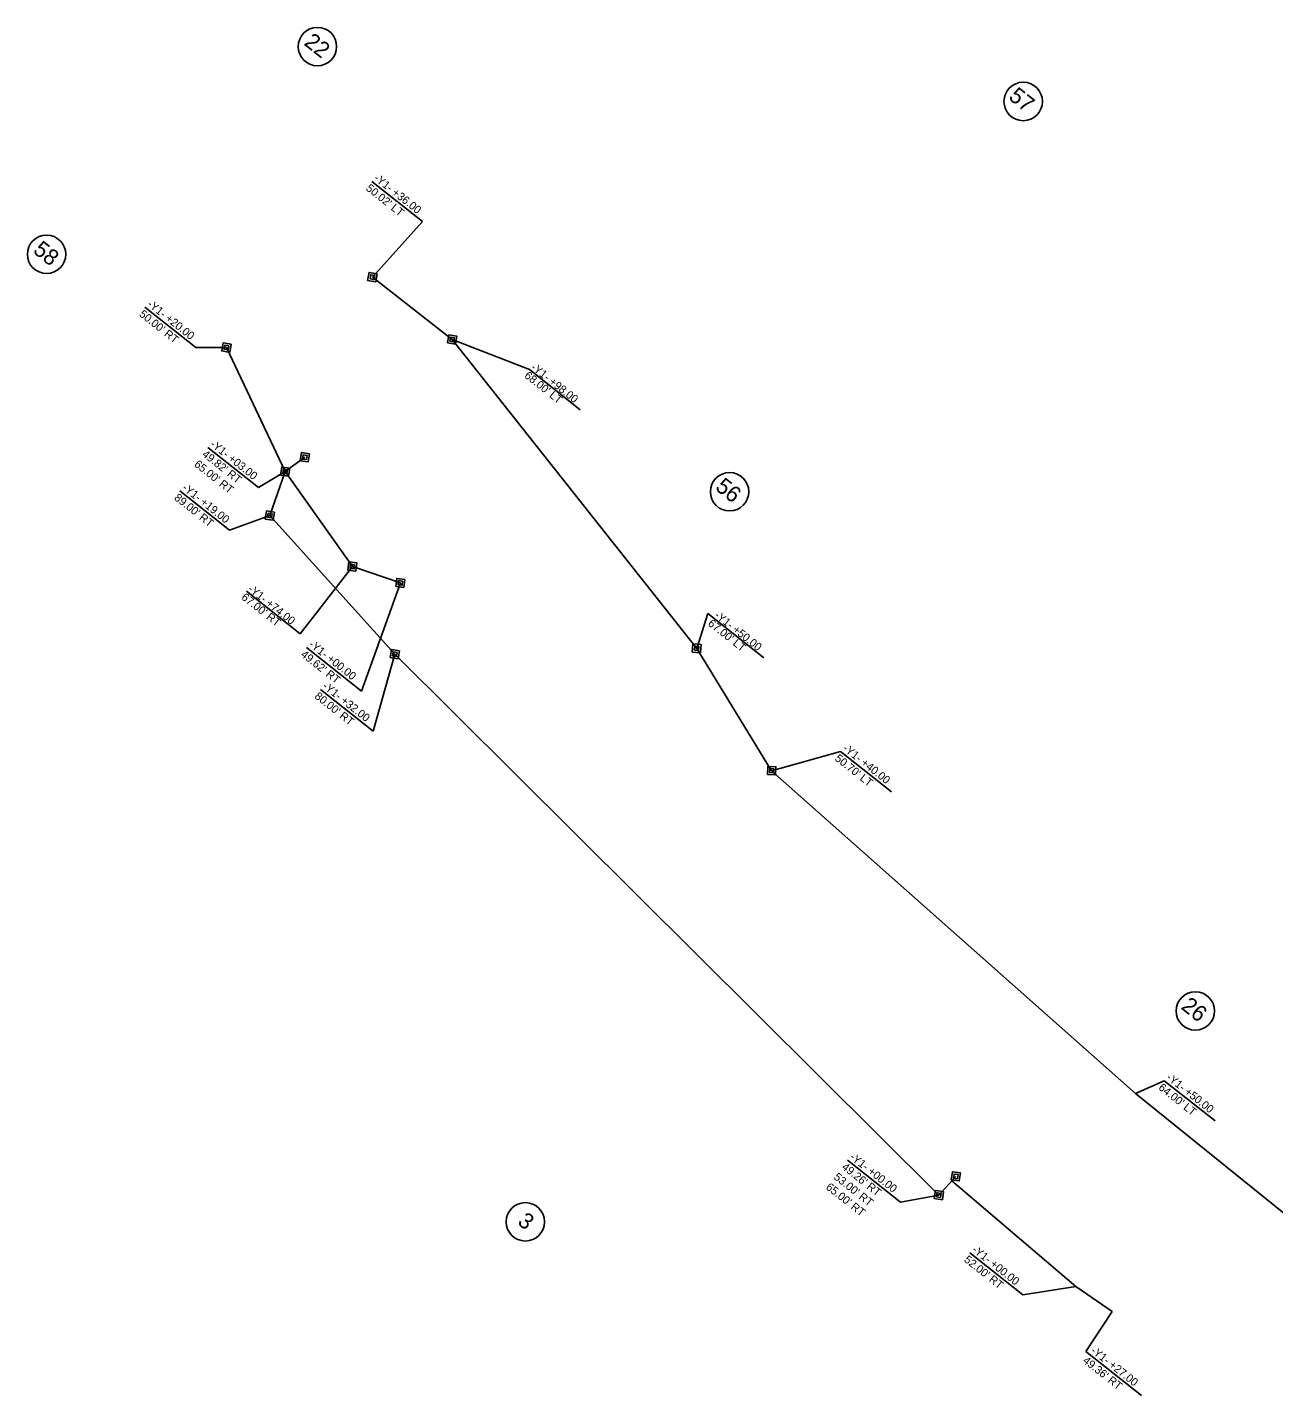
# Model space of a CAD drawing. Extents: x 1779796 to 1783527, y 810952 to 815815.
# Drawn here: x 1781662 to 1782441, y 814394 to 815249 of the extents above; entities that cross this region are included whole.
import ezdxf

# ---------------------------------------------------------------- set-up
doc = ezdxf.new("R2010")
doc.units = 0
for name, color, linetype in [('Prop Easement Construction', 7, 'Continuous'), ('Prop Easement Construction Station Offsets', 7, 'Continuous'), ('Prop Easement Permanent Drainage', 7, 'Continuous'), ('Prop Easement Permanent Drainage Station Offsets', 7, 'Continuous'), ('Prop Easement Permanent Drainage Utility', 7, 'Continuous'), ('Prop Easement Permanent Drainage Utility Station Offsets', 7, 'Continuous'), ('Prop Easement Permanent Utility', 7, 'Continuous'), ('Prop Easement Permanent Utility Station Offsets', 7, 'Continuous'), ('Prop Parcel Number CELL', 7, 'Continuous'), ('Prop Parcel Number Text', 7, 'Continuous'), ('Prop ROW Marker CELL', 7, 'Continuous'), ('Prop ROW Permanent Easement CELL', 7, 'Continuous')]:
    doc.layers.add(name, color=color, linetype=linetype)

msp = doc.modelspace()

# ---------------------------------------------------------------- linework, layer by layer
at = {"layer": 'Prop Easement Construction'}
for p, q in [((1782126.93, 814784.65), (1782354.41, 814582.96)), ((1782354.41, 814582.96), (1782533.17, 814438.56)), ((1782239.52, 814528.39), (1782317, 814462.35)), ((1782317, 814462.35), (1782339.81, 814446.82))]:
    msp.add_line(p, q, dxfattribs=at)
at = {"layer": 'Prop Easement Construction Station Offsets'}
for p, q in [((1782404.05, 814565.8), (1782372.27, 814590.96)), ((1782283.82, 814457.22), (1782250.76, 814483.39)), ((1782283.82, 814457.22), (1782317, 814462.35)), ((1782323.29, 814421.68), (1782339.81, 814446.82)), ((1782358.05, 814394.16), (1782323.29, 814421.68))]:
    msp.add_line(p, q, dxfattribs=at)
msp.add_lwpolyline([(1782372.27, 814590.96), (1782354.41, 814582.96)], dxfattribs=at)
at = {"layer": 'Prop Easement Permanent Drainage'}
for p, q in [((1781877.43, 815093.01), (1781927.33, 815054)), ((1781927.33, 815054), (1782080.08, 814861.09)), ((1781786.2, 815049), (1781822.91, 814971.49)), ((1782080.08, 814861.09), (1782126.93, 814784.65))]:
    msp.add_line(p, q, dxfattribs=at)
at = {"layer": 'Prop Easement Permanent Drainage Station Offsets'}
for p, q in [((1781908.79, 815127.71), (1781877, 815152.87)), ((1781767.08, 815049.02), (1781735.3, 815074.19)), ((1782007.33, 815010.08), (1781975.55, 815035.24)), ((1782122.04, 814855.18), (1782087.14, 814882.81)), ((1782201.84, 814771.45), (1782170.06, 814796.61))]:
    msp.add_line(p, q, dxfattribs=at)
for points in [[(1781908.79, 815127.71), (1781877.43, 815093.01)], [(1781975.55, 815035.24), (1781927.33, 815054)], [(1781767.08, 815049.02), (1781786.2, 815049)], [(1782087.14, 814882.81), (1782080.08, 814861.09)], [(1782170.06, 814796.61), (1782126.93, 814784.65)]]:
    msp.add_lwpolyline(points, dxfattribs=at)
at = {"layer": 'Prop Easement Permanent Drainage Utility'}
for p, q in [((1781835.16, 814980.46), (1781822.91, 814971.49)), ((1781822.91, 814971.49), (1781864.92, 814912.23)), ((1781864.92, 814912.23), (1781894.93, 814901.96))]:
    msp.add_line(p, q, dxfattribs=at)
at = {"layer": 'Prop Easement Permanent Drainage Utility Station Offsets'}
for p, q in [((1781806.32, 814961.57), (1781774.63, 814986.66)), ((1781832.29, 814870.15), (1781798.69, 814896.76)), ((1781870.63, 814834.39), (1781836.31, 814861.56))]:
    msp.add_line(p, q, dxfattribs=at)
for points in [[(1781806.32, 814961.57), (1781822.91, 814971.49)], [(1781832.29, 814870.15), (1781864.92, 814912.23)], [(1781870.63, 814834.39), (1781894.93, 814901.96)]]:
    msp.add_lwpolyline(points, dxfattribs=at)
at = {"layer": 'Prop Easement Permanent Utility'}
for p, q in [((1781822.91, 814971.49), (1781813.32, 814944.03)), ((1781813.32, 814944.03), (1781891.47, 814857.45)), ((1781891.47, 814857.45), (1782231.49, 814519.48)), ((1782231.49, 814519.48), (1782242.01, 814531.17))]:
    msp.add_line(p, q, dxfattribs=at)
at = {"layer": 'Prop Easement Permanent Utility Station Offsets'}
for p, q in [((1781788.04, 814935.03), (1781757.19, 814959.45)), ((1781877.97, 814809.3), (1781891.47, 814857.45)), ((1781877.97, 814809.3), (1781844.91, 814835.47)), ((1782207.41, 814515.14), (1782174.35, 814541.32)), ((1782207.41, 814515.14), (1782231.49, 814519.48))]:
    msp.add_line(p, q, dxfattribs=at)
msp.add_lwpolyline([(1781788.04, 814935.03), (1781813.32, 814944.03)], dxfattribs=at)
at = {"layer": 'Prop Parcel Number CELL'}
for p, q in [((1781843.08, 815237.09), (1781843.08, 815237.09)), ((1782284.14, 815202.78), (1782284.14, 815202.78)), ((1781673.8, 815107.31), (1781673.8, 815107.31)), ((1782100.63, 814958.93), (1782100.63, 814958.93)), ((1782391.73, 814634.53), (1782391.73, 814634.53)), ((1781973.02, 814502.77), (1781973.02, 814502.77))]:
    msp.add_line(p, q, dxfattribs=at)
for centre in [(1781843.08, 815237.09), (1782284.14, 815202.78), (1781673.8, 815107.31), (1782100.63, 814958.93), (1782391.73, 814634.53), (1781973.02, 814502.77)]:
    msp.add_circle(centre, 12, dxfattribs=at)
at = {"layer": 'Prop ROW Marker CELL'}
for p, q in [((1781877.43, 815093.01), (1781877.43, 815093.01)), ((1781927.33, 815054), (1781927.33, 815054)), ((1781786.2, 815049), (1781786.2, 815049)), ((1781835.16, 814980.46), (1781835.16, 814980.46)), ((1781822.91, 814971.49), (1781822.91, 814971.49)), ((1781813.32, 814944.03), (1781813.32, 814944.03)), ((1781864.92, 814912.23), (1781864.92, 814912.23)), ((1781894.93, 814901.96), (1781894.93, 814901.96)), ((1781891.47, 814857.45), (1781891.47, 814857.45)), ((1782080.08, 814861.09), (1782080.08, 814861.09)), ((1782126.93, 814784.65), (1782126.93, 814784.65)), ((1782242.01, 814531.17), (1782242.01, 814531.17)), ((1782231.49, 814519.48), (1782231.49, 814519.48))]:
    msp.add_line(p, q, dxfattribs=at)
at = {"layer": 'Prop ROW Permanent Easement CELL'}
for points in [[(1781874.47, 815090.95), (1781875.37, 815095.96), (1781880.38, 815095.07), (1781879.49, 815090.06)], [(1781875.95, 815091.98), (1781876.4, 815094.49), (1781878.9, 815094.04), (1781878.46, 815091.53)], [(1781789.16, 815051.05), (1781788.26, 815046.04), (1781783.25, 815046.94), (1781784.15, 815051.95)], [(1781787.68, 815050.03), (1781787.23, 815047.52), (1781784.73, 815047.97), (1781785.18, 815050.48)], [(1781924.43, 815051.88), (1781925.21, 815056.91), (1781930.24, 815056.13), (1781929.46, 815051.1)], [(1781925.88, 815052.94), (1781926.27, 815055.46), (1781928.79, 815055.06), (1781928.39, 815052.55)], [(1781838.06, 814982.58), (1781837.29, 814977.55), (1781832.26, 814978.33), (1781833.03, 814983.36)], [(1781836.61, 814981.52), (1781836.22, 814979.01), (1781833.71, 814979.39), (1781834.09, 814981.91)], [(1781825.81, 814973.62), (1781825.04, 814968.59), (1781820.01, 814969.35), (1781820.77, 814974.39)], [(1781824.36, 814972.55), (1781823.97, 814970.04), (1781821.46, 814970.42), (1781821.84, 814972.94)], [(1781816.22, 814946.17), (1781815.46, 814941.14), (1781810.43, 814941.89), (1781811.18, 814946.92)], [(1781814.77, 814945.1), (1781814.39, 814942.58), (1781811.88, 814942.96), (1781812.25, 814945.48)], [(1781867.77, 814914.43), (1781867.12, 814909.38), (1781862.07, 814910.03), (1781862.72, 814915.08)], [(1781866.35, 814913.33), (1781866.02, 814910.8), (1781863.5, 814911.13), (1781863.82, 814913.65)], [(1781897.76, 814904.19), (1781897.15, 814899.13), (1781892.1, 814899.74), (1781892.7, 814904.8)], [(1781896.34, 814903.08), (1781896.04, 814900.55), (1781893.51, 814900.85), (1781893.82, 814903.38)], [(1782077.36, 814858.73), (1782077.71, 814863.81), (1782082.79, 814863.46), (1782082.44, 814858.38)], [(1782078.72, 814859.91), (1782078.89, 814862.45), (1782081.43, 814862.28), (1782081.26, 814859.74)], [(1781894.37, 814859.59), (1781893.61, 814854.56), (1781888.58, 814855.31), (1781889.33, 814860.34)], [(1781892.92, 814858.52), (1781892.54, 814856), (1781890.03, 814856.38), (1781890.4, 814858.9)], [(1782124.3, 814782.2), (1782124.49, 814787.29), (1782129.57, 814787.1), (1782129.38, 814782.01)], [(1782125.62, 814783.42), (1782125.71, 814785.97), (1782128.25, 814785.87), (1782128.16, 814783.33)], [(1782244.91, 814533.31), (1782244.16, 814528.28), (1782239.12, 814529.03), (1782239.87, 814534.06)], [(1782243.46, 814532.24), (1782243.08, 814529.72), (1782240.57, 814530.1), (1782240.94, 814532.62)], [(1782234.38, 814521.62), (1782233.63, 814516.58), (1782228.59, 814517.33), (1782229.34, 814522.37)], [(1782232.93, 814520.55), (1782232.56, 814518.03), (1782230.04, 814518.4), (1782230.42, 814520.92)]]:
    msp.add_lwpolyline(points, close=True, dxfattribs=at)

# ---------------------------------------------------------------- texts
at = {"layer": 'Prop Easement Construction Station Offsets'}
for s, p in [("64.00' LT", (1782368.25, 814585.85)), ('-Y1- +50.00', (1782373.21, 814592.13)), ('-Y1- +00.00', (1782251.71, 814484.56)), ("52.00' RT", (1782246.74, 814478.29)), ("49.36' RT", (1782320.97, 814415.23)), ('-Y1- +27.00', (1782325.93, 814421.5))]:
    msp.add_text(s, height=5, rotation=321.63093, dxfattribs=at).set_placement(p)
at = {"layer": 'Prop Easement Permanent Drainage Station Offsets'}
for s, p in [('-Y1- +36.00', (1781877.95, 815154.04)), ("50.02' LT", (1781872.99, 815147.76)), ('-Y1- +20.00', (1781736.25, 815075.35)), ("50.00' RT", (1781731.28, 815069.08)), ("68.00' LT", (1781972, 815030.72)), ('-Y1- +98.00', (1781976.03, 815035.82)), ("67.00' LT", (1782086.7, 814875.82)), ('-Y1- +50.00', (1782090.74, 814880.92)), ("50.70' LT", (1782166.04, 814791.5)), ('-Y1- +40.00', (1782171, 814797.77))]:
    msp.add_text(s, height=5, rotation=321.63093, dxfattribs=at).set_placement(p)
at = {"layer": 'Prop Easement Permanent Drainage Utility Station Offsets'}
for s, p in [('-Y1- +03.00', (1781775.58, 814987.82)), ("49.82' RT", (1781770.61, 814981.55)), ("65.00' RT", (1781765.64, 814975.28)), ('-Y1- +74.00', (1781799.17, 814897.33)), ("67.00' RT", (1781795.14, 814892.24)), ('-Y1- +00.00', (1781837.26, 814862.73)), ("49.62' RT", (1781832.29, 814856.45))]:
    msp.add_text(s, height=5, rotation=321.63093, dxfattribs=at).set_placement(p)
at = {"layer": 'Prop Easement Permanent Utility Station Offsets'}
for s, p in [("89.00' RT", (1781753.17, 814954.34)), ('-Y1- +19.00', (1781758.14, 814960.62)), ('-Y1- +32.00', (1781845.86, 814836.64)), ("80.00' RT", (1781840.89, 814830.36)), ("49.26' RT", (1782170.33, 814536.21)), ('-Y1- +00.00', (1782175.29, 814542.48)), ("53.00' RT", (1782165.36, 814529.94)), ("65.00' RT", (1782160.4, 814523.67))]:
    msp.add_text(s, height=5, rotation=321.63093, dxfattribs=at).set_placement(p)
at = {"layer": 'Prop Parcel Number Text'}
for s, p in [('22', (1781834.14, 815238.54)), ('57', (1782274.45, 815204.66)), ('58', (1781664.81, 815108.67)), ('56', (1782091.14, 814960.65)), ('26', (1782382.24, 814636.25)), ('3', (1781967.58, 814501.73))]:
    msp.add_text(s, height=10, rotation=321.63093, dxfattribs=at).set_placement(p)

doc.saveas('drawing.dxf')
